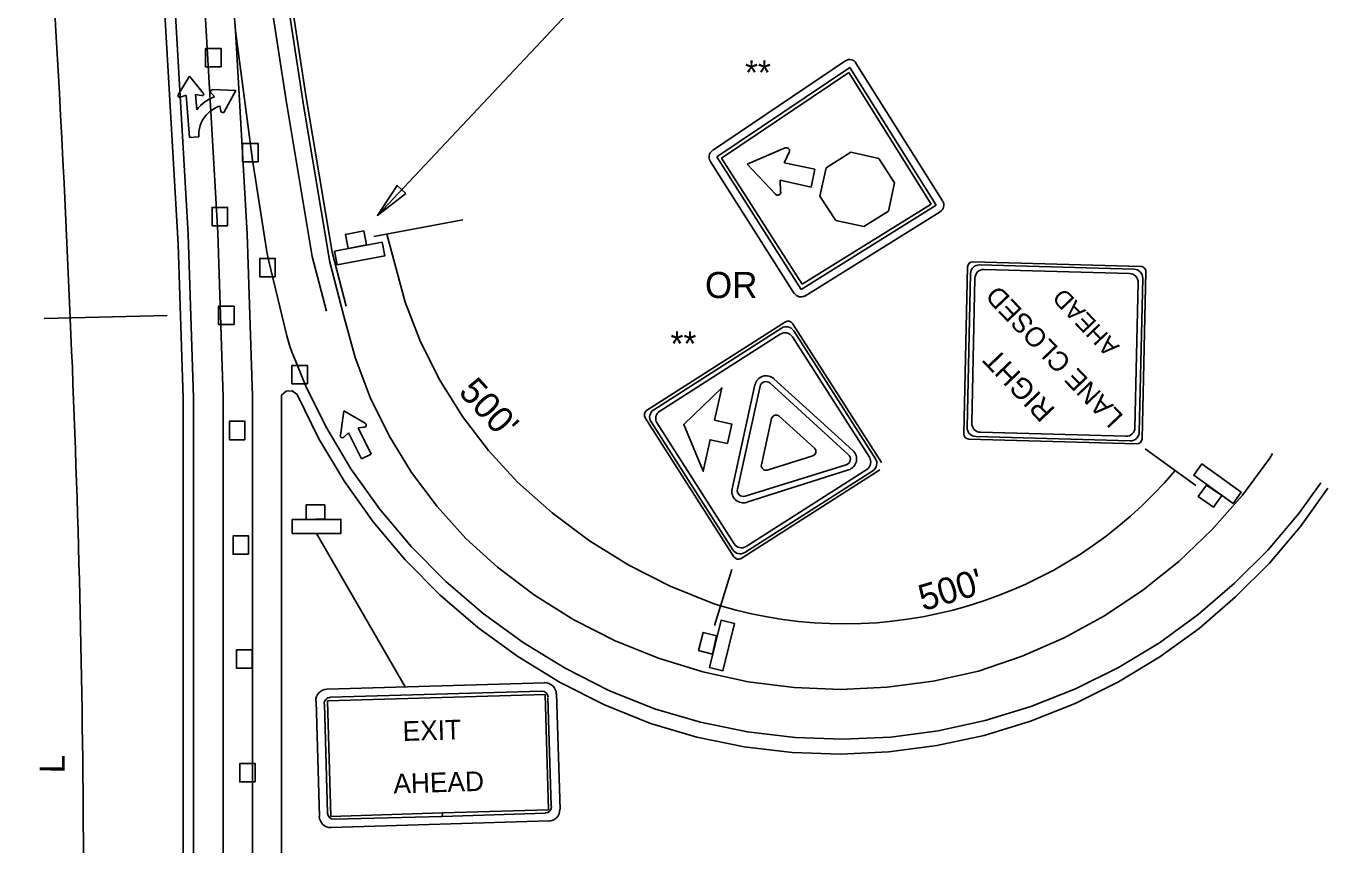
# Model space of a CAD drawing. Extents: x 612.48 to 619.85, y 611.03 to 621.01.
# Drawn here: x 615.13 to 618.118, y 616.834 to 618.714 of the extents above; entities that cross this region are included whole.
import ezdxf

# ---------------------------------------------------------------- set-up
doc = ezdxf.new("R2010")
doc.units = 0
for name, color, linetype in [('DETL-DIMS', 7, 'Continuous'), ('DETL-LINE', 7, 'Continuous'), ('DETL-NOTE', 7, 'Continuous'), ('USER-BORD', 7, 'Continuous')]:
    doc.layers.add(name, color=color, linetype=linetype)

# ---------------------------------------------------------------- blocks, each defined once
blk = doc.blocks.new('SIGN14')
at = {"layer": 'USER-BORD'}
for points in [[(-0.0134, 0.0182), (0.011, 0.0189), (0.011, 0.0371), (-0.0134, 0.0371)], [(-0.0314, 0.0182), (-0.0314, 0), (0.032, 0), (0.032, 0.0182)]]:
    blk.add_lwpolyline(points, close=True, dxfattribs=at)

msp = doc.modelspace()

# ---------------------------------------------------------------- linework, layer by layer
at = {"layer": 'DETL-DIMS'}
for p, q in [((615.9365, 618.2792), (616.7846, 619.1808)), ((615.9287, 618.2311), (616.1328, 618.269)), ((615.1719, 618.0425), (615.454, 618.0493)), ((617.8151, 617.659), (617.6988, 617.7434)), ((616.7106, 617.3381), (616.7498, 617.4663)), ((615.2618, 616.8441), (615.2618, 615.9454))]:
    msp.add_line(p, q, dxfattribs=at)
msp.add_lwpolyline([(616.0017, 618.3298), (615.9818, 618.3482), (615.9366, 618.2792)], close=True, dxfattribs=at)
msp.add_lwpolyline([(615.9579, 618.2365), (616.0002, 618.0805), (616.0358, 617.9888), (616.0798, 617.901), (616.1318, 617.8176), (616.1914, 617.7394), (616.2581, 617.6672), (616.3376, 617.5962), (616.423, 617.5323), (616.5136, 617.476), (616.6086, 617.4278), (616.7075, 617.3879), (616.7242, 617.3828)], dxfattribs=at)
for centre, radius, start, end in [((573.0337, 616.2812), 42.2346, 2.39201, 4.63613), ((584.4626, 616.6669), 30.7997, 0.32969, 2.55949), ((617.0083, 618.337), 0.9955, 253.4214, 319.7192)]:
    msp.add_arc(centre, radius, start, end, dxfattribs=at)
at = {"layer": 'DETL-LINE'}
for p, q in [((615.611, 618.7031), (615.5961, 618.8831)), ((615.6484, 618.4183), (615.611, 618.7031)), ((615.4793, 618.5561), (615.5051, 618.5989)), ((615.5051, 618.5989), (615.5369, 618.5603)), ((615.4976, 618.5554), (615.4844, 618.5506)), ((615.5052, 618.4586), (615.4976, 618.5554)), ((615.4976, 618.5554), (615.4976, 618.5554)), ((615.5328, 618.5544), (615.5192, 618.5573)), ((615.5192, 618.5573), (615.522, 618.5222)), ((615.5624, 618.5526), (615.554, 618.5606)), ((615.557, 618.5682), (615.6115, 618.5662)), ((615.6115, 618.5662), (615.5852, 618.5175)), ((615.577, 618.5189), (615.5747, 618.5307)), ((615.5265, 618.4651), (615.5269, 618.4602)), ((615.5269, 618.4602), (615.5052, 618.4586)), ((616.7849, 618.3973), (616.8723, 618.4344)), ((615.6822, 618.2009), (615.6494, 618.4114)), ((616.8816, 618.4244), (616.87, 618.4001)), ((616.9667, 618.3885), (617.023, 618.4245)), ((617.023, 618.4245), (617.0873, 618.4104)), ((617.0873, 618.4104), (617.1234, 618.3544)), ((616.8502, 618.3279), (616.7849, 618.3973)), ((616.87, 618.4001), (616.9409, 618.3858)), ((616.9409, 618.3858), (616.9318, 618.3442)), ((616.9524, 618.3238), (616.9667, 618.3885)), ((616.9318, 618.3446), (616.8608, 618.3603)), ((616.8608, 618.3603), (616.862, 618.3336)), ((617.1234, 618.3544), (617.1094, 618.2888)), ((616.8502, 618.3279), (616.8502, 618.3279)), ((616.9885, 618.2678), (616.9524, 618.3238)), ((617.1094, 618.2888), (617.0532, 618.2536)), ((617.0532, 618.2536), (616.9885, 618.2678)), ((615.7289, 618.0026), (615.6868, 618.1776)), ((617.6886, 618.1622), (617.3033, 618.1729)), ((617.3189, 618.1657), (617.6732, 618.1558)), ((617.2912, 618.1614), (617.2827, 617.778)), ((617.2902, 617.7925), (617.298, 618.1459)), ((617.308, 618.1354), (617.3007, 617.8024)), ((617.6627, 618.146), (617.3289, 618.1552)), ((617.6932, 618.1349), (617.6853, 617.7816)), ((617.6918, 617.7666), (617.7003, 618.15)), ((617.6753, 617.792), (617.6827, 618.125)), ((616.8732, 618.0347), (616.5545, 617.8311)), ((616.5707, 617.833), (616.8644, 618.0206)), ((617.0934, 617.7117), (616.8895, 618.0311)), ((616.8921, 618.0145), (617.0797, 617.7208)), ((616.8613, 618.0068), (616.5846, 617.83)), ((617.0659, 617.7239), (616.889, 618.0006)), ((615.7724, 617.8873), (615.7425, 617.9605)), ((616.8379, 617.8943), (617.0175, 617.73)), ((617.0278, 617.7397), (616.8468, 617.9044)), ((615.65, 617.8646), (615.65, 612.6411)), ((615.7162, 617.8667), (615.7162, 612.6432)), ((616.6396, 617.7992), (616.7269, 617.8837)), ((616.7506, 617.6514), (616.8032, 617.8905)), ((616.7629, 617.651), (616.815, 617.887)), ((615.4908, 617.8594), (615.4908, 612.6359)), ((615.5143, 617.8602), (615.5143, 612.6367)), ((615.5826, 617.8624), (615.5826, 612.6389)), ((615.8515, 617.7744), (615.8594, 617.8304)), ((615.8594, 617.8304), (615.9086, 617.8024)), ((616.551, 617.8149), (616.755, 617.4955)), ((616.7522, 617.5116), (616.5646, 617.8053)), ((616.5846, 617.83), (616.5845, 617.83)), ((616.8413, 617.8128), (616.818, 617.707)), ((616.8413, 617.8128), (616.8413, 617.8128)), ((616.9397, 617.7452), (616.8585, 617.8183)), ((615.8703, 617.7803), (615.8596, 617.7699)), ((615.8703, 617.7803), (615.9, 617.7206)), ((615.9071, 617.7935), (615.8923, 617.7913)), ((615.8923, 617.7913), (615.9219, 617.7311)), ((616.5784, 617.8021), (616.7552, 617.5255)), ((616.6396, 617.7992), (616.6844, 617.6918)), ((617.3007, 617.8024), (617.3007, 617.8024)), ((617.3206, 617.7814), (617.6544, 617.7722)), ((616.6574, 617.7615), (616.6574, 617.7615)), ((617.2943, 617.7658), (617.6796, 617.755)), ((617.6644, 617.7618), (617.3102, 617.7716)), ((615.9219, 617.7311), (615.9, 617.7206)), ((616.8313, 617.6948), (616.9358, 617.7274)), ((616.7712, 617.4919), (617.0899, 617.6955)), ((617.0736, 617.6931), (616.7799, 617.5054)), ((617.0122, 617.7064), (616.7806, 617.6348)), ((616.783, 617.5194), (617.0598, 617.6961)), ((617.018, 617.695), (616.7844, 617.6206)), ((615.7969, 617.5493), (616.0002, 617.1968)), ((616.3206, 617.2058), (615.8211, 617.1918)), ((615.822, 617.1646), (616.3214, 617.1795)), ((616.3128, 617.1867), (615.8291, 617.1731)), ((616.3128, 617.1867), (616.3128, 617.1867)), ((616.3214, 617.1795), (616.3295, 616.9141)), ((615.8149, 617.1569), (615.8224, 616.9072)), ((615.83, 616.899), (615.822, 617.1646)), ((616.3354, 616.9227), (616.328, 617.1714)), ((616.086, 616.9078), (615.83, 616.899)), ((616.0852, 616.8994), (616.086, 616.9078)), ((616.086, 616.9078), (616.0852, 616.8994)), ((616.3295, 616.9141), (616.086, 616.9078)), ((615.8376, 616.893), (616.0852, 616.8994)), ((616.0852, 616.8994), (616.3223, 616.9066))]:
    msp.add_line(p, q, dxfattribs=at)
for points in [[(615.59, 619.6294), (615.6541, 619.0199), (615.7271, 618.543), (615.7872, 618.1851), (615.8194, 618.0593)], [(615.6364, 619.6343), (615.7004, 619.0258), (615.7732, 618.5504), (615.8329, 618.1947), (615.8646, 618.0709)], [(615.4082, 619.6041), (615.4661, 618.8583), (615.5021, 618.2366), (615.5143, 617.8602)], [(615.4763, 619.6094), (615.5343, 618.8629), (615.5704, 618.2397), (615.5826, 617.8624)], [(615.6312, 619.6117), (615.6951, 619.0032), (615.7679, 618.5278), (615.8276, 618.1721), (615.8592, 618.0483)], [(615.6312, 619.6117), (615.6951, 619.0032), (615.7679, 618.5278), (615.8276, 618.1721), (615.8592, 618.0483)], [(615.6312, 619.6117), (615.6951, 619.0032), (615.7679, 618.5278), (615.8276, 618.1721), (615.8592, 618.0483)], [(615.3854, 619.5801), (615.4434, 618.8345), (615.4793, 618.2132), (615.4908, 617.8594)], [(615.611, 618.7031), (615.6379, 618.2374), (615.65, 617.8646)], [(617.0117, 618.635), (616.7053, 618.4281)], [(616.7153, 618.4136), (617.0206, 618.6193)], [(617.0206, 618.6193), (617.2187, 618.303)], [(617.2332, 618.313), (617.035, 618.6289)], [(616.7262, 618.4112), (617.0184, 618.6075)], [(617.0184, 618.6075), (617.2074, 618.3055)], [(616.7004, 618.404), (616.8934, 618.1002)], [(616.9094, 618.109), (616.7153, 618.4136)], [(616.9112, 618.1214), (616.7262, 618.4112)], [(617.2187, 618.303), (616.9094, 618.109)], [(617.2074, 618.3055), (616.9112, 618.1214)], [(616.9176, 618.0941), (617.2282, 618.2877)], [(615.8592, 618.0483), (615.8853, 617.9534), (615.92, 617.8615), (615.9632, 617.7732), (616.0145, 617.6894), (616.0734, 617.6107), (616.1394, 617.5378), (616.212, 617.4715), (616.2972, 617.4075), (616.3876, 617.351), (616.4826, 617.3026), (616.5814, 617.2625), (616.6833, 617.2311), (616.7875, 617.2087), (616.8933, 617.1952), (616.9998, 617.191), (617.1063, 617.196), (617.212, 617.2101), (617.3161, 617.2332), (617.4162, 617.2672), (617.5129, 617.3096), (617.6056, 617.3603), (617.6935, 617.4189), (617.776, 617.4849), (617.8524, 617.5579), (617.9222, 617.6372), (617.9848, 617.7223), (617.991, 617.7324)], [(615.7162, 617.8667), (615.7268, 617.8757), (615.7407, 617.8764), (615.7522, 617.8685), (615.8025, 617.7663), (615.8609, 617.6684), (615.9269, 617.5756), (616.0003, 617.4885), (616.0804, 617.4075), (616.1669, 617.3333), (616.259, 617.2662), (616.3562, 617.2069), (616.458, 617.1556), (616.5635, 617.1126), (616.67, 617.0815), (616.7787, 617.0593), (616.8889, 617.0461), (616.9998, 617.0422), (617.1107, 617.0474), (617.2207, 617.0619), (617.3291, 617.0854), (617.4353, 617.1178), (617.5383, 617.1588), (617.6377, 617.2083), (617.7326, 617.2659), (617.8223, 617.3311), (617.9064, 617.4035), (617.9842, 617.481), (618.0553, 617.5648), (618.1183, 617.6531)], [(615.7724, 617.8873), (615.818, 617.7945), (615.8759, 617.6975), (615.9414, 617.6054), (616.0142, 617.519), (616.0937, 617.4387), (616.1794, 617.365), (616.2708, 617.2986), (616.3672, 617.2397), (616.4681, 617.1888), (616.5726, 617.1463), (616.6781, 617.1154), (616.7859, 617.0934), (616.8951, 617.0804), (617.005, 617.0765), (617.1149, 617.0817), (617.224, 617.096), (617.3315, 617.1193), (617.4367, 617.1514), (617.5389, 617.1921), (617.6373, 617.2412), (617.7314, 617.2982), (617.8204, 617.3628), (617.9038, 617.4347), (617.9809, 617.5116), (618.0513, 617.5946), (618.1016, 617.665)], [(616.3557, 616.915), (616.3476, 617.1814)], [(615.7957, 617.1638), (615.8038, 616.8993)], [(615.8307, 616.8738), (616.3301, 616.8889)]]:
    msp.add_lwpolyline(points, dxfattribs=at)
for points in [[(615.5779, 618.6205), (615.5424, 618.6205), (615.5424, 618.6627), (615.5779, 618.6627)], [(615.6626, 618.4024), (615.6271, 618.4024), (615.6271, 618.4446), (615.6626, 618.4446)], [(615.5928, 618.2555), (615.5573, 618.2555), (615.5573, 618.2977), (615.5928, 618.2977)], [(615.702, 618.1386), (615.6666, 618.1386), (615.6666, 618.1808), (615.702, 618.1808)], [(615.6075, 618.029), (615.572, 618.029), (615.572, 618.0712), (615.6075, 618.0712)], [(615.7758, 617.8927), (615.7403, 617.8927), (615.7403, 617.9349), (615.7758, 617.9349)], [(616.7402, 617.7554), (616.7501, 617.8002), (616.7104, 617.8089), (616.7269, 617.8837), (616.6396, 617.7992), (616.6844, 617.6918), (616.7003, 617.7642)], [(615.6324, 617.7644), (615.5969, 617.7644), (615.5969, 617.8066), (615.6324, 617.8066)], [(615.6408, 617.5014), (615.6053, 617.5014), (615.6053, 617.5436), (615.6408, 617.5436)], [(615.6488, 617.2397), (615.6134, 617.2397), (615.6134, 617.2819), (615.6488, 617.2819)], [(615.6563, 616.9786), (615.6208, 616.9786), (615.6208, 617.0208), (615.6563, 617.0208)]]:
    msp.add_lwpolyline(points, close=True, dxfattribs=at)
for centre, radius, start, end in [((615.483, 618.5542), 0.00386, 149.7687, 289.7669), ((615.5943, 618.4669), 0.0908, 110.3599, 142.6419), ((615.534, 618.558), 0.00386, 259.2592, 39.2575), ((615.5578, 618.5632), 0.0047, 96.5887, 217.8979), ((615.6039, 618.4529), 0.0829, 110.3599, 131.8675), ((615.5926, 618.4655), 0.0659, 131.8675, 180.4441), ((615.5817, 618.5203), 0.0047, 198.8719, 320.1811), ((615.9375, 618.4563), 0.2916, 187.4865, 188.8574), ((615.9703, 618.2458), 0.2916, 188.8574, 193.5241), ((616.0124, 618.0708), 0.2916, 193.5241, 202.2339), ((615.8562, 617.7734), 0.00481, 171.9519, 314.2122), ((615.9064, 617.7982), 0.00481, 278.2122, 60.4725), ((616.3209, 617.1802), 0.0263, 1.7294, 91.7294), ((615.8215, 617.1651), 0.0263, 91.7294, 181.7294), ((616.3137, 617.1726), 0.0147, 1.7294, 91.7294), ((615.829, 617.158), 0.0147, 91.7294, 181.7294), ((615.8366, 616.9075), 0.0147, 181.7294, 271.7294), ((616.3213, 616.9221), 0.0147, 271.7294, 1.7294), ((616.3289, 616.9149), 0.0263, 271.7294, 1.7294), ((615.8295, 616.8999), 0.0263, 181.7294, 271.7294)]:
    msp.add_arc(centre, radius, start, end, dxfattribs=at)
for centre, major_axis, ratio, start_param, end_param in [((617.0208, 618.6198), (-0.0171, 0.0038), 0.999922, 3.926991, 5.497787), ((616.8755, 618.4275), (-0.00713, 0.00157), 0.999922, 2.884299, 5.327729), ((616.7153, 618.4136), (-0.0171, 0.0038), 0.999922, 5.54537, 7.042948), ((616.8551, 618.333), (-0.00713, 0.00157), 0.999922, 0.964393, 3.407823), ((617.2191, 618.303), (0.0171, -0.0038), 0.999922, 5.421015, 7.068583), ((617.3031, 618.161), (-0.00996, 0.0066), 0.993733, 5.272637, 6.843433), ((617.3184, 618.1453), (-0.0171, 0.0113), 0.993733, 5.272637, 6.843433), ((617.6883, 618.1503), (-0.00996, 0.0066), 0.993733, 3.70184, 5.272637), ((617.3284, 618.1348), (-0.0171, 0.0113), 0.993733, 5.272637, 6.843433), ((617.6622, 618.1255), (-0.0171, 0.0113), 0.993733, 3.70184, 5.272637), ((617.6727, 618.1355), (-0.0171, 0.0113), 0.993733, 3.70184, 5.272637), ((616.9088, 618.1096), (-0.0171, 0.0038), 0.999922, 0.785398, 2.312744), ((616.8721, 617.9898), (-0.0196, 0.0043), 0.999922, 3.926991, 5.497787), ((616.8752, 618.0037), (-0.0196, 0.0043), 0.999922, 3.926991, 5.497787), ((616.8796, 618.0248), (-0.0115, 0.0025), 0.999922, 3.926991, 5.497787), ((616.8291, 617.8848), (-0.0258, 0.0057), 0.999922, 4.191063, 6.283185), ((616.8285, 617.884), (-0.0136, 0.003), 0.999922, 4.18832, 6.283185), ((616.5609, 617.8212), (-0.0115, 0.0025), 0.999922, 5.497787, 7.068583), ((616.5815, 617.8161), (-0.0196, 0.0043), 0.999922, 5.497787, 7.068583), ((616.5954, 617.813), (-0.0196, 0.0043), 0.999922, 5.497787, 7.068583), ((616.8516, 617.8105), (-0.0102, 0.0023), 0.999922, 4.195513, 6.283185), ((617.2946, 617.7776), (-0.00996, 0.0066), 0.993733, 0.560248, 2.131044), ((617.3106, 617.792), (-0.0171, 0.0113), 0.993733, 0.560248, 2.131044), ((617.3211, 617.8019), (-0.0171, 0.0113), 0.993733, 0.560248, 2.131044), ((617.6549, 617.7926), (-0.0171, 0.0113), 0.993733, 2.131044, 3.70184), ((617.6648, 617.7821), (-0.0171, 0.0113), 0.993733, 2.131044, 3.70184), ((616.9327, 617.7374), (-0.0102, 0.0023), 0.999922, 2.089942, 4.195513), ((617.6798, 617.7669), (-0.00996, 0.0066), 0.993733, 2.131044, 3.70184), ((617.0082, 617.7197), (-0.0136, 0.003), 0.999922, 2.087614, 4.18832), ((617.01, 617.7201), (-0.0258, 0.0057), 0.999922, 2.096108, 4.191063), ((617.0489, 617.713), (-0.0196, 0.0043), 0.999922, 2.356194, 3.926991), ((617.0628, 617.71), (-0.0196, 0.0043), 0.999922, 2.356194, 3.926991), ((616.8282, 617.7048), (-0.0102, 0.0023), 0.999922, 0, 2.089942), ((616.7764, 617.6457), (-0.0258, 0.0057), 0.999922, 0, 2.096108), ((616.7765, 617.648), (-0.0136, 0.003), 0.999922, 0, 2.087614), ((616.7691, 617.5224), (-0.0196, 0.0043), 0.999922, 0.785398, 2.356194), ((616.7721, 617.5362), (-0.0196, 0.0043), 0.999922, 0.785398, 2.356194), ((616.7649, 617.5018), (-0.0115, 0.0025), 0.999922, 0.785398, 2.356194)]:
    msp.add_ellipse(centre, major_axis=major_axis, ratio=ratio, start_param=start_param, end_param=end_param, dxfattribs=at)

# ---------------------------------------------------------------- block references
for p, xscale, yscale, rotation in [((615.8982, 618.176), 1.7600000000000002, 1.7600000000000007, 10.4348953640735), ((617.8746, 617.6759), 1.7600000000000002, 1.7600000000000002, 144.14768166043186), ((616.7428, 617.2874), 1.7600000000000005, 1.7600000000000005, 76.11631033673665)]:
    msp.add_blockref('SIGN14', p, dxfattribs=dict(at, xscale=xscale, yscale=yscale, rotation=rotation))
at = {"layer": 'DETL-LINE', "xscale": 1.7600000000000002, "yscale": 1.7600000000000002}
msp.add_blockref('SIGN14', (615.7964, 617.5493), dxfattribs=at)

# ---------------------------------------------------------------- texts
at = {"layer": 'DETL-LINE'}
for s, height, rotation, p in [('LANE CLOSED', 0.04479, 133.6474, (617.6509, 617.8185)), ('AHEAD', 0.04079, 133.6474, (617.6418, 617.9793)), ('RIGHT', 0.04764, 133.6474, (617.4946, 617.834)), ('EXIT', 0.04516, 1.7294, (615.9951, 617.0725)), ('AHEAD', 0.04516, 1.7294, (615.9738, 616.9519))]:
    msp.add_text(s, height=height, rotation=rotation, dxfattribs=at).set_placement(p)
at = {"layer": 'DETL-NOTE'}
for s, height, p in [('**', 0.057, (616.7803, 618.5788)), ('OR', 0.06, (616.6885, 618.0896)), ('**', 0.057, (616.6093, 617.9563))]:
    msp.add_text(s, height=height, dxfattribs=at).set_placement(p)
for s, height, rotation, p in [("500'", 0.06, 312.7049, (616.1205, 617.8722)), ("500'", 0.06, 16.5703, (617.1891, 617.3704)), ('L', 0.057, 89.5698, (615.2186, 616.9983))]:
    msp.add_text(s, height=height, rotation=rotation, dxfattribs=at).set_placement(p)

doc.saveas('drawing.dxf')
